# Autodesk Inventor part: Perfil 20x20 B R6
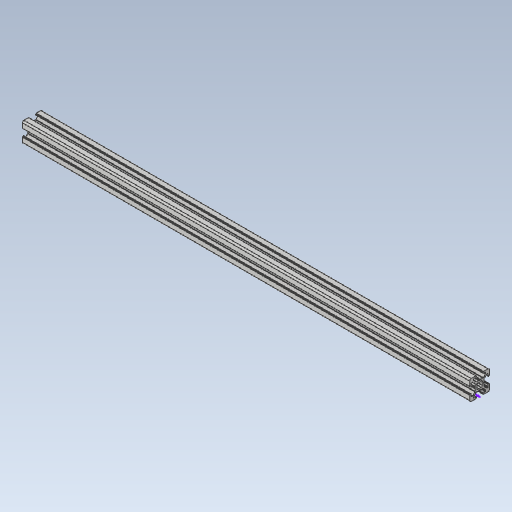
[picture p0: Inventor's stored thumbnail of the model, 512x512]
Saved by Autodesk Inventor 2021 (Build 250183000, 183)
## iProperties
Created: 2020-12
Part Number: Perfil 20x20 B R6
Material: Genérico
Document SubType Name: Modeling
Designer: ATOUZA
Density: 1 g/cm^3
Appearance: Valor por defecto
Author: ATOUZA
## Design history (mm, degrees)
sketch "Boceto1"
  geometry: L1 (4.5, 0.954)-(4.5, 3.232); L2 (4.646, 3.586)-(6.914, 5.854); L3 (7.268, 6)-(8, 6); L4 (8.5, 5.5)-(8.5, 3.6); L5 (9, 3.1)-(9.3, 3.1); L6 (9.5, 3.3)-(9.5, 3.65); L7 (9.5, 3.65)-(9.8, 3.65); L8 (10, 3.85)-(10, 8.5); L9 (8.5, 10)-(3.85, 10); L10 (3.65, 9.8)-(3.65, 9.5); L11 (3.65, 9.5)-(3.3, 9.5); L12 (3.1, 9.3)-(3.1, 9); L13 (3.6, 8.5)-(5.5, 8.5); L14 (6, 8)-(6, 7.268); L15 (5.854, 6.914)-(3.586, 4.646); L16 (3.232, 4.5)-(0.954, 4.5); L17 (0.854, 4.473)-(0.1, 4.038); L18 (-0.1, 4.038)-(-0.854, 4.473); L19 (-0.954, 4.5)-(-3.232, 4.5); L20 (-3.586, 4.646)-(-5.854, 6.914); L21 (-6, 7.268)-(-6, 8); L22 (-5.5, 8.5)-(-3.6, 8.5); L23 (-3.1, 9)-(-3.1, 9.3); L24 (-3.3, 9.5)-(-3.65, 9.5); L25 (-3.65, 9.5)-(-3.65, 9.8); L26 (-3.85, 10)-(-8.5, 10); L27 (-10, 8.5)-(-10, 3.85); L28 (-9.8, 3.65)-(-9.5, 3.65); L29 (-9.5, 3.65)-(-9.5, 3.3); L30 (-9.3, 3.1)-(-9, 3.1); L31 (-8.5, 3.6)-(-8.5, 5.5); L32 (-8, 6)-(-7.268, 6); L33 (-6.914, 5.854)-(-4.646, 3.586); L34 (-4.5, 3.232)-(-4.5, 0.954); L35 (-4.473, 0.854)-(-4.038, 0.1); L36 (-4.038, -0.1)-(-4.473, -0.854); L37 (-4.5, -0.954)-(-4.5, -3.232); L38 (-4.646, -3.586)-(-6.914, -5.854); L39 (-7.268, -6)-(-8, -6); L40 (-8.5, -5.5)-(-8.5, -3.6); L41 (-9, -3.1)-(-9.3, -3.1); L42 (-9.5, -3.3)-(-9.5, -3.65); L43 (-9.5, -3.65)-(-9.8, -3.65); L44 (-10, -3.85)-(-10, -8.5); L45 (-8.5, -10)-(-3.85, -10); L46 (-3.65, -9.8)-(-3.65, -9.5); L47 (-3.65, -9.5)-(-3.3, -9.5); L48 (-3.1, -9.3)-(-3.1, -9); L49 (-3.6, -8.5)-(-5.5, -8.5); L50 (-6, -8)-(-6, -7.268); L51 (-5.854, -6.914)-(-3.586, -4.646); L52 (-3.232, -4.5)-(-0.954, -4.5); L53 (1.258, -2.445)-(1.914, -2.99); L54 (2.992, -1.91)-(2.445, -1.258); L55 (2.445, 1.258)-(2.992, 1.91); L56 (1.914, 2.99)-(1.258, 2.445); L57 (-1.258, 2.445)-(-1.914, 2.99); L58 (-2.992, 1.91)-(-2.445, 1.258); L59 (-2.445, -1.258)-(-2.992, -1.91); L60 (-1.914, -2.99)-(-1.258, -2.445); L61 (1.258, -2.445)-(1.914, -2.99); L62 (2.992, -1.91)-(2.445, -1.258); L63 (2.445, 1.258)-(2.992, 1.91); L64 (1.914, 2.99)-(1.258, 2.445)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; A1 r 0.5 centre (5, 3.232) between (4.646, 3.586) and (4.5, 3.232); A2 r 0.5 centre (7.268, 5.5) between (7.268, 6) and (6.914, 5.854); A3 r 0.5 centre (8, 5.5) between (8.5, 5.5) and (8, 6); A4 r 0.5 centre (9, 3.6) between (8.5, 3.6) and (9, 3.1); A5 r 0.2 centre (9.3, 3.3) between (9.3, 3.1) and (9.5, 3.3); A6 r 0.2 centre (9.8, 3.85) between (9.8, 3.65) and (10, 3.85); A7 r 1.5 centre (8.5, 8.5) between (10, 8.5) and (8.5, 10); A8 r 0.2 centre (3.85, 9.8) between (3.85, 10) and (3.65, 9.8); A9 r 0.2 centre (3.3, 9.3) between (3.3, 9.5) and (3.1, 9.3); A10 r 0.5 centre (3.6, 9) between (3.1, 9) and (3.6, 8.5); A11 r 0.5 centre (5.5, 8) between (6, 8) and (5.5, 8.5); A12 r 0.5 centre (5.5, 7.268) between (5.854, 6.914) and (6, 7.268); A13 r 0.5 centre (3.232, 5) between (3.232, 4.5) and (3.586, 4.646); A14 r 0.2 centre (0.954, 4.3) between (0.954, 4.5) and (0.854, 4.473); A15 r 0.2 centre (0, 4.211) between (-0.1, 4.038) and (0.1, 4.038); A16 r 0.2 centre (-0.954, 4.3) between (-0.854, 4.473) and (-0.954, 4.5); A17 r 0.5 centre (-3.232, 5) between (-3.586, 4.646) and (-3.232, 4.5); A18 r 0.5 centre (-5.5, 7.268) between (-6, 7.268) and (-5.854, 6.914); A19 r 0.5 centre (-5.5, 8) between (-5.5, 8.5) and (-6, 8); A20 r 0.5 centre (-3.6, 9) between (-3.6, 8.5) and (-3.1, 9); A21 r 0.2 centre (-3.3, 9.3) between (-3.1, 9.3) and (-3.3, 9.5); A22 r 0.2 centre (-3.85, 9.8) between (-3.65, 9.8) and (-3.85, 10); A23 r 1.5 centre (-8.5, 8.5) between (-8.5, 10) and (-10, 8.5); A24 r 0.2 centre (-9.8, 3.85) between (-10, 3.85) and (-9.8, 3.65); A25 r 0.2 centre (-9.3, 3.3) between (-9.5, 3.3) and (-9.3, 3.1); A26 r 0.5 centre (-9, 3.6) between (-9, 3.1) and (-8.5, 3.6); A27 r 0.5 centre (-8, 5.5) between (-8, 6) and (-8.5, 5.5); A28 r 0.5 centre (-7.268, 5.5) between (-6.914, 5.854) and (-7.268, 6); A29 r 0.5 centre (-5, 3.232) between (-4.5, 3.232) and (-4.646, 3.586); A30 r 0.2 centre (-4.3, 0.954) between (-4.5, 0.954) and (-4.473, 0.854); A31 r 0.2 centre (-4.211, 0) between (-4.038, -0.1) and (-4.038, 0.1); A32 r 0.2 centre (-4.3, -0.954) between (-4.473, -0.854) and (-4.5, -0.954); A33 r 0.5 centre (-5, -3.232) between (-4.646, -3.586) and (-4.5, -3.232); A34 r 0.5 centre (-7.268, -5.5) between (-7.268, -6) and (-6.914, -5.854); A35 r 0.5 centre (-8, -5.5) between (-8.5, -5.5) and (-8, -6); A36 r 0.5 centre (-9, -3.6) between (-8.5, -3.6) and (-9, -3.1); A37 r 0.2 centre (-9.3, -3.3) between (-9.3, -3.1) and (-9.5, -3.3); A38 r 0.2 centre (-9.8, -3.85) between (-9.8, -3.65) and (-10, -3.85); A39 r 1.5 centre (-8.5, -8.5) between (-10, -8.5) and (-8.5, -10); A40 r 0.2 centre (-3.85, -9.8) between (-3.85, -10) and (-3.65, -9.8); A41 r 0.2 centre (-3.3, -9.3) between (-3.3, -9.5) and (-3.1, -9.3); A42 r 0.5 centre (-3.6, -9) between (-3.1, -9) and (-3.6, -8.5); A43 r 0.5 centre (-5.5, -8) between (-6, -8) and (-5.5, -8.5); A44 r 0.5 centre (-5.5, -7.268) between (-5.854, -6.914) and (-6, -7.268); A45 r 0.5 centre (-3.232, -5) between (-3.232, -4.5) and (-3.586, -4.646); A46 r 2.75 centre (0, 0) between (-1.258, -2.445) and (1.258, -2.445); A47 r 3.55 centre (0, 0) between (1.914, -2.99) and (2.992, -1.91); A48 r 2.75 centre (0, 0) between (2.445, -1.258) and (2.445, 1.258); A49 r 3.55 centre (0, 0) between (2.992, 1.91) and (1.914, 2.99); A50 r 2.75 centre (0, 0) between (1.258, 2.445) and (-1.258, 2.445); A51 r 3.55 centre (0, 0) between (-1.914, 2.99) and (-2.992, 1.91); A52 r 2.75 centre (0, 0) between (-2.445, 1.258) and (-2.445, -1.258); A53 r 3.55 centre (0, 0) between (-2.992, -1.91) and (-1.914, -2.99); A54 r 2.75 centre (0, 0) between (-1.258, -2.445) and (1.258, -2.445); A55 r 3.55 centre (0, 0) between (1.914, -2.99) and (2.992, -1.91); A56 r 2.75 centre (0, 0) between (2.445, -1.258) and (2.445, 1.258); A57 r 3.55 centre (0, 0) between (2.992, 1.91) and (1.914, 2.99); A58 r 2.75 centre (0, 0) between (1.258, 2.445) and (-1.258, 2.445); A59 r 3.55 centre (0, 0) between (-1.914, 2.99) and (-2.992, 1.91); A60 r 2.75 centre (0, 0) between (-2.445, 1.258) and (-2.445, -1.258); A61 r 3.55 centre (0, 0) between (-2.992, -1.91) and (-1.914, -2.99); A62 r 0.5 centre (-8, -5.5) between (-8.5, -5.5) and (-8, -6); A63 r 0.2 centre (-4.211, 0) between (-4.038, -0.1) and (-4.038, 0.1); A64 r 0.5 centre (-7.268, 5.5) between (-6.914, 5.854) and (-7.268, 6)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; 1 further point
  constraints: 324 end point, 198 point on circle, 99 centre point, 2 point on line, 6 other
extrude "Extrusión1" new body sketch "Boceto1" distance "d0" = 450; taper "d1" = 0 deg
sketch "Boceto5"
  geometry: L1 (0, -3.85)-(450, -3.85)
  constraints: 2 end point
node "Sólido1"
